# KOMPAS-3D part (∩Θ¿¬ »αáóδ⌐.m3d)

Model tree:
1. Эскиз:1
2. Операция выдавливания:1
     Расстояние 1 = 36.6; Расстояние 2 = 1
3. Эскиз:2
4. Вырезать элемент выдавливания:1
     Расстояние 1 = 28.2
5. Фаска:1
     Угол = 71.5651; Длина 1 = 5; Длина 2 = 15
6. Скругление:1
     Радиус = 2
7. Эскиз:3
8. Операция выдавливания:2
     Расстояние 1 = 0.3; Расстояние 2 = 1
9. Скругление:2
     Радиус = 0.3
10. Скругление:3
     Радиус = 0.3
11. Эскиз:4
12. Операция выдавливания:3
     Расстояние 1 = 1; Расстояние 2 = 1
13. Эскиз:5
14. Операция выдавливания:4
     Расстояние 1 = 2; Расстояние 2 = 1
15. Скругление:4
     Радиус = 0.5
16. Скругление:5
     Радиус = 0.5
17. Эскиз:6
18. Вырезать элемент выдавливания:2
     Расстояние 1 = 0.3
19. Скругление:6
     Радиус = 0.3
20. Скругление:7
     Радиус = 0.3
21. Эскиз:7
22. Операция выдавливания:5
     Расстояние 1 = 2; Расстояние 2 = 1
23. Скругление:8
     Радиус = 0.3
24. Эскиз:8
25. Операция выдавливания:6
     Расстояние 1 = 0.5; Расстояние 2 = 1
26. Ломаная:1
27. Перпендикулярная плоскость:1
28. Эскиз:9
29. Кинематическая операция:1
     Толщина стенки 1 = 1; Толщина стенки 2 = 1

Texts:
  Сплав АЛ8  ГОСТ 1583-93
